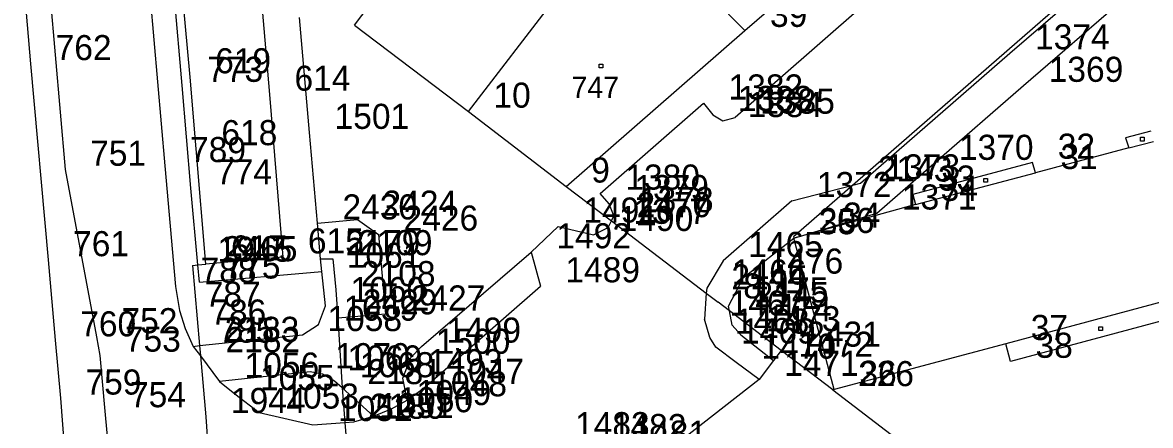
# Model space of a CAD drawing. Extents: x -822293 to -820259, y -1071573 to -1068794.
# Drawn here: x -821466.4 to -821376.4, y -1070045.9 to -1070013.7 of the extents above; entities that cross this region are included whole.
import ezdxf

# ---------------------------------------------------------------- set-up
doc = ezdxf.new("R2010")
doc.units = 0
for name, color, linetype in [('Vrstva 11', 7, 'Continuous'), ('Vrstva 2', 7, 'Continuous'), ('Vrstva 3', 7, 'Continuous'), ('Vrstva 6', 7, 'Continuous'), ('Vrstva 8', 7, 'Continuous'), ('Vrstva 9', 7, 'Continuous')]:
    doc.layers.add(name, color=color, linetype=linetype)

# ---------------------------------------------------------------- blocks, each defined once
blk = doc.blocks.new('Z402')
at = {"layer": 'Vrstva 2'}
for p, q in [((-10, 10), (20, 10)), ((-10, -20), (-10, 10)), ((20, 10), (20, -20)), ((20, -20), (-10, -20))]:
    blk.add_line(p, q, dxfattribs=at)

msp = doc.modelspace()

# ---------------------------------------------------------------- linework, layer by layer
at = {"layer": 'Vrstva 2'}
for p, q in [((-821361.05, -1069992.64), (-821404.92, -1070030.82)), ((-821408.79, -1070014.39), (-821393.85, -1070001.36)), ((-821439.92, -1070013.94), (-821431.86, -1070003.26)), ((-821414.88, -1070008.21), (-821408.79, -1070014.39)), ((-821430.85, -1070020.83), (-821422.71, -1070010.25)), ((-821439.92, -1070013.94), (-821430.85, -1070020.83)), ((-821423.05, -1070026.8), (-821408.79, -1070014.39)), ((-821430.85, -1070020.83), (-821423.05, -1070026.8)), ((-821376.42, -1070022.4), (-821378.43, -1070022.94)), ((-821378.43, -1070022.94), (-821378.18, -1070023.74)), ((-821378.18, -1070023.74), (-821385.62, -1070025.72)), ((-821385.84, -1070024.9), (-821395.4, -1070027.44)), ((-821385.62, -1070025.72), (-821385.84, -1070024.9)), ((-821423.05, -1070026.8), (-821419.43, -1070029.56)), ((-821395.4, -1070027.44), (-821395.18, -1070028.26)), ((-821395.18, -1070028.26), (-821402.96, -1070030.39)), ((-821419.43, -1070029.56), (-821411.87, -1070035.32)), ((-821404.92, -1070030.82), (-821404.89, -1070030.92)), ((-821402.96, -1070030.39), (-821404.89, -1070030.92)), ((-821401.66, -1070043), (-821404.89, -1070030.92)), ((-821411.87, -1070035.32), (-821410.92, -1070036.04)), ((-821410.03, -1070036.72), (-821410.92, -1070036.04)), ((-821405.9, -1070039.88), (-821410.03, -1070036.72)), ((-821372.94, -1070036.84), (-821387.61, -1070040.77)), ((-821387.99, -1070039.35), (-821401.66, -1070043)), ((-821387.61, -1070040.77), (-821387.99, -1070039.35)), ((-821406.52, -1070040.69), (-821407.66, -1070042.21)), ((-821405.9, -1070039.88), (-821406.52, -1070040.69)), ((-821401.77, -1070043.03), (-821405.9, -1070039.88)), ((-821407.66, -1070042.21), (-821416.96, -1070049.45)), ((-821401.66, -1070043), (-821401.77, -1070043.03)), ((-821401.77, -1070043.03), (-821361.25, -1070073.95))]:
    msp.add_line(p, q, dxfattribs=at)
at = {"layer": 'Vrstva 3'}
for p, q in [((-821453.05, -1070018.09), (-821454.56, -1070001.09)), ((-821448.27, -1070000.96), (-821446.72, -1070019.48)), ((-821456.65, -1070006.9), (-821455.05, -1070025.17)), ((-821387.65, -1070016.18), (-821377.66, -1070007.5)), ((-821464.47, -1070008.88), (-821463.02, -1070025.46)), ((-821466.41, -1070009.71), (-821465.77, -1070017.04)), ((-821453.68, -1070018.77), (-821454.43, -1070010.11)), ((-821386.56, -1070018.77), (-821378.62, -1070011.87)), ((-821399.45, -1070012.46), (-821409.57, -1070021.31)), ((-821443.52, -1070022.52), (-821444.31, -1070013.33)), ((-821399.58, -1070026.55), (-821387.65, -1070016.18)), ((-821465.77, -1070017.04), (-821464.38, -1070032.67)), ((-821452.55, -1070023.82), (-821453.05, -1070018.09)), ((-821452.98, -1070026.95), (-821453.68, -1070018.77)), ((-821393.72, -1070024.99), (-821386.56, -1070018.77)), ((-821446.72, -1070019.48), (-821445.65, -1070032.45)), ((-821420.33, -1070027.36), (-821412.1, -1070020.18)), ((-821412.1, -1070020.18), (-821411.35, -1070021.09)), ((-821411.35, -1070021.09), (-821410.56, -1070021.58)), ((-821410.56, -1070021.58), (-821409.57, -1070021.31)), ((-821442.89, -1070029.74), (-821443.52, -1070022.52)), ((-821378.18, -1070023.74), (-821376.21, -1070023.22)), ((-821451.79, -1070033.01), (-821452.55, -1070023.82)), ((-821455.05, -1070025.17), (-821454.21, -1070034.78)), ((-821398.27, -1070028.95), (-821393.72, -1070024.99)), ((-821463.02, -1070025.46), (-821460.52, -1070038.81)), ((-821395.18, -1070028.26), (-821385.62, -1070025.72)), ((-821452.43, -1070033.07), (-821452.98, -1070026.95)), ((-821405.05, -1070027.96), (-821400.19, -1070026.71)), ((-821400.19, -1070026.71), (-821399.58, -1070026.55)), ((-821419.61, -1070028.2), (-821420.33, -1070027.36)), ((-821405.05, -1070027.96), (-821410.53, -1070032.73)), ((-821419.24, -1070029.16), (-821419.61, -1070028.2)), ((-821404.89, -1070030.92), (-821398.27, -1070028.95)), ((-821442.89, -1070029.74), (-821439.7, -1070029.44)), ((-821442.64, -1070032.59), (-821442.89, -1070029.74)), ((-821439.7, -1070029.44), (-821438.02, -1070030.63)), ((-821419.69, -1070030.09), (-821419.43, -1070029.56)), ((-821419.43, -1070029.56), (-821419.24, -1070029.16)), ((-821438.02, -1070030.63), (-821437.45, -1070037)), ((-821425.83, -1070032.04), (-821423.68, -1070029.99)), ((-821423.68, -1070029.99), (-821420.86, -1070030.66)), ((-821420.86, -1070030.66), (-821419.69, -1070030.09)), ((-821408.9, -1070034.06), (-821404.89, -1070030.92)), ((-821445.65, -1070032.45), (-821451.79, -1070033.01)), ((-821442.55, -1070033.59), (-821442.64, -1070032.59)), ((-821442.64, -1070032.59), (-821441.66, -1070032.59)), ((-821441.66, -1070032.59), (-821441.42, -1070035.06)), ((-821434.6, -1070039.56), (-821425.83, -1070032.04)), ((-821425.83, -1070032.04), (-821425.11, -1070034.75)), ((-821464.38, -1070032.67), (-821463.81, -1070039.06)), ((-821452.86, -1070033.11), (-821452.43, -1070033.07)), ((-821452.86, -1070033.11), (-821452.29, -1070039.5)), ((-821452.43, -1070033.07), (-821451.79, -1070033.01)), ((-821452.3, -1070034.45), (-821452.43, -1070033.07)), ((-821410.53, -1070032.73), (-821411.84, -1070034.93)), ((-821452.3, -1070034.45), (-821442.55, -1070033.59)), ((-821442.25, -1070036.33), (-821442.55, -1070033.59)), ((-821410.09, -1070036.35), (-821408.9, -1070034.06)), ((-821454.21, -1070034.78), (-821453.88, -1070036.7)), ((-821441.42, -1070035.06), (-821441.27, -1070037.31)), ((-821434.37, -1070042.85), (-821425.11, -1070034.75)), ((-821411.87, -1070035.32), (-821412.02, -1070037.4)), ((-821411.84, -1070034.93), (-821411.87, -1070035.32)), ((-821373.32, -1070035.42), (-821387.99, -1070039.35)), ((-821453.88, -1070036.7), (-821453.43, -1070038.12)), ((-821442.8, -1070037.81), (-821442.25, -1070036.33)), ((-821437.45, -1070037), (-821441.27, -1070037.31)), ((-821410.03, -1070036.72), (-821410.09, -1070036.35)), ((-821409.82, -1070037.86), (-821410.03, -1070036.72)), ((-821444.09, -1070038.64), (-821442.8, -1070037.81)), ((-821441.27, -1070037.31), (-821440.91, -1070042.87)), ((-821411.6, -1070038.85), (-821412.02, -1070037.4)), ((-821409.82, -1070037.86), (-821409.12, -1070038.65)), ((-821460.52, -1070038.81), (-821460.25, -1070040.28)), ((-821453.43, -1070038.12), (-821452.79, -1070039.56)), ((-821452.29, -1070039.5), (-821444.09, -1070038.64)), ((-821411.1, -1070039.63), (-821411.6, -1070038.85)), ((-821409.12, -1070038.65), (-821406.52, -1070040.69)), ((-821463.81, -1070039.06), (-821463.39, -1070043.7)), ((-821452.79, -1070039.56), (-821452.29, -1070039.5)), ((-821452.79, -1070039.56), (-821452.22, -1070040.32)), ((-821452.29, -1070039.5), (-821452.22, -1070040.32)), ((-821435.45, -1070040.45), (-821434.6, -1070039.56)), ((-821409.48, -1070040.84), (-821411.1, -1070039.63)), ((-821460.25, -1070040.28), (-821459.84, -1070044.71)), ((-821452.22, -1070040.32), (-821451.79, -1070045.17)), ((-821452.22, -1070040.32), (-821450.7, -1070042.35)), ((-821436.07, -1070042.08), (-821435.45, -1070040.45)), ((-821443.47, -1070041.6), (-821450.7, -1070042.35)), ((-821442.49, -1070041.78), (-821443.47, -1070041.6)), ((-821407.66, -1070042.21), (-821409.48, -1070040.84)), ((-821450.7, -1070042.35), (-821449.47, -1070043.35)), ((-821441.52, -1070042.32), (-821442.49, -1070041.78)), ((-821440.91, -1070042.87), (-821441.52, -1070042.32)), ((-821435.72, -1070043.84), (-821436.07, -1070042.08)), ((-821449.47, -1070043.35), (-821447.53, -1070044.82)), ((-821440.91, -1070042.87), (-821438.43, -1070045.11)), ((-821440.91, -1070042.87), (-821440.71, -1070045.63)), ((-821435.72, -1070043.84), (-821434.37, -1070042.85)), ((-821463.39, -1070043.7), (-821462.99, -1070048.72)), ((-821436.98, -1070044.54), (-821435.72, -1070043.84)), ((-821459.84, -1070044.71), (-821459.32, -1070050.51)), ((-821451.79, -1070045.17), (-821451.5, -1070049.66)), ((-821447.53, -1070044.82), (-821443.25, -1070045.81)), ((-821439.98, -1070045.57), (-821438.43, -1070045.11)), ((-821438.43, -1070045.11), (-821436.98, -1070044.54)), ((-821443.25, -1070045.81), (-821440.71, -1070045.63)), ((-821440.71, -1070045.63), (-821439.98, -1070045.57)), ((-821440.71, -1070045.63), (-821440.47, -1070048.6))]:
    msp.add_line(p, q, dxfattribs=at)
at = {"layer": 'Vrstva 8'}
for p, q in [((-821439.92, -1070013.94), (-821439.92, -1070013.94)), ((-821408.79, -1070014.39), (-821408.79, -1070014.39)), ((-821387.65, -1070016.18), (-821387.65, -1070016.18)), ((-821465.77, -1070017.04), (-821465.77, -1070017.04)), ((-821453.05, -1070018.09), (-821453.05, -1070018.09)), ((-821453.68, -1070018.77), (-821453.68, -1070018.77)), ((-821386.56, -1070018.77), (-821386.56, -1070018.77)), ((-821446.72, -1070019.48), (-821446.72, -1070019.48)), ((-821430.85, -1070020.83), (-821430.85, -1070020.83)), ((-821412.1, -1070020.18), (-821412.1, -1070020.18)), ((-821411.35, -1070021.09), (-821411.35, -1070021.09)), ((-821410.56, -1070021.58), (-821410.56, -1070021.58)), ((-821409.57, -1070021.31), (-821409.57, -1070021.31)), ((-821443.52, -1070022.52), (-821443.52, -1070022.52)), ((-821378.43, -1070022.94), (-821378.43, -1070022.94)), ((-821452.55, -1070023.82), (-821452.55, -1070023.82)), ((-821378.18, -1070023.74), (-821378.18, -1070023.74)), ((-821455.05, -1070025.17), (-821455.05, -1070025.17)), ((-821393.72, -1070024.99), (-821393.72, -1070024.99)), ((-821385.84, -1070024.9), (-821385.84, -1070024.9)), ((-821463.02, -1070025.46), (-821463.02, -1070025.46)), ((-821385.62, -1070025.72), (-821385.62, -1070025.72)), ((-821452.98, -1070026.95), (-821452.98, -1070026.95)), ((-821423.05, -1070026.8), (-821423.05, -1070026.8)), ((-821400.19, -1070026.71), (-821400.19, -1070026.71)), ((-821399.58, -1070026.55), (-821399.58, -1070026.55)), ((-821420.33, -1070027.36), (-821420.33, -1070027.36)), ((-821405.05, -1070027.96), (-821405.05, -1070027.96)), ((-821395.4, -1070027.44), (-821395.4, -1070027.44)), ((-821419.61, -1070028.2), (-821419.61, -1070028.2)), ((-821398.27, -1070028.95), (-821398.27, -1070028.95)), ((-821395.18, -1070028.26), (-821395.18, -1070028.26)), ((-821442.89, -1070029.74), (-821442.89, -1070029.74)), ((-821439.7, -1070029.44), (-821439.7, -1070029.44)), ((-821419.43, -1070029.56), (-821419.43, -1070029.56)), ((-821419.24, -1070029.16), (-821419.24, -1070029.16)), ((-821438.02, -1070030.63), (-821438.02, -1070030.63)), ((-821423.68, -1070029.99), (-821423.68, -1070029.99)), ((-821420.86, -1070030.66), (-821420.86, -1070030.66)), ((-821419.69, -1070030.09), (-821419.69, -1070030.09)), ((-821404.92, -1070030.82), (-821404.92, -1070030.82)), ((-821402.96, -1070030.39), (-821402.96, -1070030.39)), ((-821404.89, -1070030.92), (-821404.89, -1070030.92)), ((-821445.65, -1070032.45), (-821445.65, -1070032.45)), ((-821442.64, -1070032.59), (-821442.64, -1070032.59)), ((-821441.66, -1070032.59), (-821441.66, -1070032.59)), ((-821425.83, -1070032.04), (-821425.83, -1070032.04)), ((-821464.38, -1070032.67), (-821464.38, -1070032.67)), ((-821452.86, -1070033.11), (-821452.86, -1070033.11)), ((-821452.43, -1070033.07), (-821452.43, -1070033.07)), ((-821451.79, -1070033.01), (-821451.79, -1070033.01)), ((-821410.53, -1070032.73), (-821410.53, -1070032.73)), ((-821442.55, -1070033.59), (-821442.55, -1070033.59)), ((-821408.9, -1070034.06), (-821408.9, -1070034.06)), ((-821454.21, -1070034.78), (-821454.21, -1070034.78)), ((-821452.3, -1070034.45), (-821452.3, -1070034.45)), ((-821441.42, -1070035.06), (-821441.42, -1070035.06)), ((-821425.11, -1070034.75), (-821425.11, -1070034.75)), ((-821411.87, -1070035.32), (-821411.87, -1070035.32)), ((-821411.84, -1070034.93), (-821411.84, -1070034.93)), ((-821410.92, -1070036.04), (-821410.92, -1070036.04)), ((-821453.88, -1070036.7), (-821453.88, -1070036.7)), ((-821442.25, -1070036.33), (-821442.25, -1070036.33)), ((-821437.45, -1070037), (-821437.45, -1070037)), ((-821410.09, -1070036.35), (-821410.09, -1070036.35)), ((-821410.03, -1070036.72), (-821410.03, -1070036.72)), ((-821442.8, -1070037.81), (-821442.8, -1070037.81)), ((-821441.27, -1070037.31), (-821441.27, -1070037.31)), ((-821412.02, -1070037.4), (-821412.02, -1070037.4)), ((-821409.82, -1070037.86), (-821409.82, -1070037.86)), ((-821460.52, -1070038.81), (-821460.52, -1070038.81)), ((-821453.43, -1070038.12), (-821453.43, -1070038.12)), ((-821444.09, -1070038.64), (-821444.09, -1070038.64)), ((-821411.6, -1070038.85), (-821411.6, -1070038.85)), ((-821409.12, -1070038.65), (-821409.12, -1070038.65)), ((-821463.81, -1070039.06), (-821463.81, -1070039.06)), ((-821452.79, -1070039.56), (-821452.79, -1070039.56)), ((-821452.29, -1070039.5), (-821452.29, -1070039.5)), ((-821434.6, -1070039.56), (-821434.6, -1070039.56)), ((-821411.1, -1070039.63), (-821411.1, -1070039.63)), ((-821387.99, -1070039.35), (-821387.99, -1070039.35)), ((-821460.25, -1070040.28), (-821460.25, -1070040.28)), ((-821452.22, -1070040.32), (-821452.22, -1070040.32)), ((-821435.45, -1070040.45), (-821435.45, -1070040.45)), ((-821406.52, -1070040.69), (-821406.52, -1070040.69)), ((-821405.9, -1070039.88), (-821405.9, -1070039.88)), ((-821443.47, -1070041.6), (-821443.47, -1070041.6)), ((-821409.48, -1070040.84), (-821409.48, -1070040.84)), ((-821387.61, -1070040.77), (-821387.61, -1070040.77)), ((-821450.7, -1070042.35), (-821450.7, -1070042.35)), ((-821442.49, -1070041.78), (-821442.49, -1070041.78)), ((-821441.52, -1070042.32), (-821441.52, -1070042.32)), ((-821436.07, -1070042.08), (-821436.07, -1070042.08)), ((-821407.66, -1070042.21), (-821407.66, -1070042.21)), ((-821449.47, -1070043.35), (-821449.47, -1070043.35)), ((-821440.91, -1070042.87), (-821440.91, -1070042.87)), ((-821434.37, -1070042.85), (-821434.37, -1070042.85)), ((-821401.77, -1070043.03), (-821401.77, -1070043.03)), ((-821401.66, -1070043), (-821401.66, -1070043)), ((-821463.39, -1070043.7), (-821463.39, -1070043.7)), ((-821435.72, -1070043.84), (-821435.72, -1070043.84)), ((-821459.84, -1070044.71), (-821459.84, -1070044.71)), ((-821451.79, -1070045.17), (-821451.79, -1070045.17)), ((-821447.53, -1070044.82), (-821447.53, -1070044.82)), ((-821438.43, -1070045.11), (-821438.43, -1070045.11)), ((-821436.98, -1070044.54), (-821436.98, -1070044.54)), ((-821443.25, -1070045.81), (-821443.25, -1070045.81)), ((-821440.71, -1070045.63), (-821440.71, -1070045.63)), ((-821439.98, -1070045.57), (-821439.98, -1070045.57))]:
    msp.add_line(p, q, dxfattribs=at)

# ---------------------------------------------------------------- block references
at = {"layer": 'Vrstva 11', "xscale": 0.01, "yscale": 0.01}
for p in [(-821420.33, -1070017.15), (-821377.14, -1070022.99), (-821389.63, -1070026.27), (-821380.46, -1070038.09)]:
    msp.add_blockref('Z402', p, dxfattribs=at)

# ---------------------------------------------------------------- texts
at = {"layer": 'Vrstva 6'}
msp.add_text('747', height=1.7, dxfattribs=at).set_placement((-821422.626, -1070019.75))
at = {"layer": 'Vrstva 9'}
for s, p in [('39', (-821406.79, -1070014.09)), ('1374', (-821385.65, -1070015.88)), ('762', (-821463.77, -1070016.74)), ('619', (-821451.05, -1070017.79)), ('773', (-821451.68, -1070018.47)), ('614', (-821444.72, -1070019.18)), ('1369', (-821384.56, -1070018.47)), ('1382', (-821410.1, -1070019.88)), ('10', (-821428.85, -1070020.53)), ('1383', (-821409.35, -1070020.79)), ('1385', (-821407.57, -1070021.01)), ('1384', (-821408.56, -1070021.28)), ('1501', (-821441.52, -1070022.22)), ('618', (-821450.55, -1070023.52)), ('1370', (-821391.72, -1070024.69)), ('32', (-821383.84, -1070024.6)), ('751', (-821461.02, -1070025.16)), ('789', (-821453.05, -1070024.87)), ('31', (-821383.62, -1070025.42)), ('9', (-821421.05, -1070026.5)), ('2143', (-821398.19, -1070026.41)), ('1373', (-821397.58, -1070026.25)), ('774', (-821450.98, -1070026.65)), ('1380', (-821418.33, -1070027.06)), ('33', (-821393.4, -1070027.14)), ('1379', (-821417.61, -1070027.9)), ('1372', (-821403.05, -1070027.66)), ('34', (-821393.18, -1070027.96)), ('2424', (-821437.7, -1070029.14)), ('1378', (-821417.24, -1070028.86)), ('1371', (-821396.27, -1070028.65)), ('2430', (-821440.89, -1070029.44)), ('1491', (-821421.68, -1070029.69)), ('1377', (-821417.69, -1070029.79)), ('2470', (-821417.43, -1070029.26)), ('34', (-821400.96, -1070030.09)), ('2426', (-821436.02, -1070030.33)), ('1490', (-821418.86, -1070030.36)), ('35', (-821402.89, -1070030.62)), ('206', (-821402.92, -1070030.52)), ('1492', (-821423.83, -1070031.74)), ('761', (-821462.38, -1070032.37)), ('1945', (-821450.86, -1070032.81)), ('2465', (-821450.43, -1070032.77)), ('617', (-821449.79, -1070032.71)), ('615', (-821443.65, -1070032.15)), ('2179', (-821440.64, -1070032.29)), ('2109', (-821439.66, -1070032.29)), ('1465', (-821408.53, -1070032.43)), ('1061', (-821440.55, -1070033.29)), ('788', (-821452.21, -1070034.48)), ('775', (-821450.3, -1070034.15)), ('1489', (-821423.11, -1070034.45)), ('1466', (-821409.84, -1070034.63)), ('1476', (-821406.9, -1070033.76)), ('2108', (-821439.42, -1070034.76)), ('2144', (-821409.87, -1070035.02)), ('787', (-821451.88, -1070036.4)), ('1060', (-821440.25, -1070036.03)), ('8', (-821408.92, -1070035.74)), ('2145', (-821408.03, -1070036.42)), ('1475', (-821408.09, -1070036.05)), ('2429', (-821439.27, -1070037.01)), ('2427', (-821435.45, -1070036.7)), ('1467', (-821410.02, -1070037.1)), ('786', (-821451.43, -1070037.82)), ('1059', (-821440.8, -1070037.51)), ('1474', (-821407.82, -1070037.56)), ('760', (-821461.81, -1070038.76)), ('752', (-821458.52, -1070038.51)), ('1058', (-821442.09, -1070038.34)), ('1468', (-821409.6, -1070038.55)), ('1473', (-821407.12, -1070038.35)), ('37', (-821385.99, -1070039.05)), ('753', (-821458.25, -1070039.98)), ('785', (-821450.79, -1070039.26)), ('2183', (-821450.29, -1070039.2)), ('2182', (-821450.22, -1070040.02)), ('1499', (-821432.6, -1070039.26)), ('1469', (-821409.1, -1070039.33)), ('2431', (-821403.9, -1070039.58)), ('1500', (-821433.45, -1070040.15)), ('1470', (-821407.48, -1070040.54)), ('1472', (-821404.52, -1070040.39)), ('38', (-821385.61, -1070040.47)), ('1070', (-821441.47, -1070041.3)), ('1069', (-821440.49, -1070041.48)), ('1493', (-821434.07, -1070041.78)), ('1056', (-821448.7, -1070042.05)), ('1068', (-821439.52, -1070042.02)), ('2181', (-821438.91, -1070042.57)), ('1047', (-821432.37, -1070042.55)), ('1471', (-821405.66, -1070041.91)), ('226', (-821399.77, -1070042.73)), ('36', (-821399.66, -1070042.7)), ('759', (-821461.39, -1070043.4)), ('1055', (-821447.47, -1070043.05)), ('1048', (-821433.72, -1070043.54)), ('754', (-821457.84, -1070044.41)), ('1053', (-821445.53, -1070044.52)), ('1049', (-821434.98, -1070044.24)), ('1944', (-821449.79, -1070044.87)), ('2180', (-821438.71, -1070045.33)), ('1051', (-821437.98, -1070045.27)), ('1050', (-821436.43, -1070044.81)), ('1052', (-821441.25, -1070045.51)), ('1483', (-821422.34, -1070046.8)), ('1482', (-821419.41, -1070046.95)), ('1481', (-821417.77, -1070047.47))]:
    msp.add_text(s, height=2, dxfattribs=at).set_placement(p)

doc.saveas('drawing.dxf')
